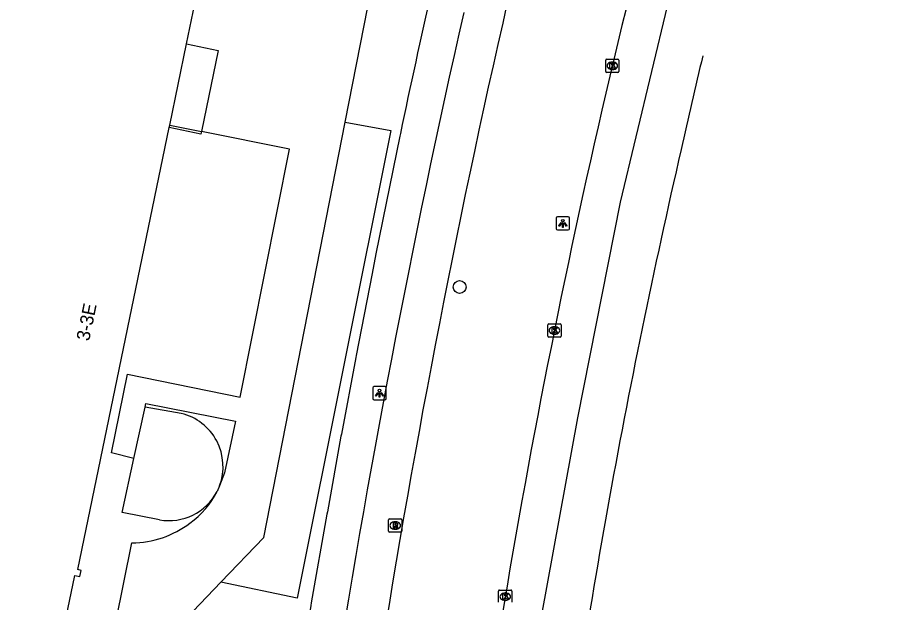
# Model space of a CAD drawing. Extents: x 161243 to 161752, y 384138 to 384885.
# Drawn here: x 161439.4 to 161506.3, y 384193.1 to 384237.2 of the extents above; entities that cross this region are included whole.
import ezdxf

# ---------------------------------------------------------------- set-up
doc = ezdxf.new("R2010")
doc.units = 0
for name, color, linetype in [('IMGEO_Boom', 7, 'Continuous'), ('IMGEO_Fietspad_gesloten', 7, 'Continuous'), ('IMGEO_Kolk', 7, 'Continuous'), ('IMGEO_Lichtpunt', 7, 'Continuous'), ('IMGEO_Muur', 7, 'Continuous'), ('IMGEO_Pand', 7, 'Continuous'), ('IMGEO_Pand_nummerreeks', 7, 'Continuous'), ('IMGEO_Parkeervlak_open', 7, 'Continuous'), ('IMGEO_Rijbaan_lokaal_gesloten', 7, 'Continuous'), ('IMGEO_Rijbaan_lokaal_open', 7, 'Continuous'), ('IMGEO_Rioolput', 7, 'Continuous'), ('IMGEO_Voetpad_open', 7, 'Continuous')]:
    doc.layers.add(name, color=color, linetype=linetype)

msp = doc.modelspace()

# ---------------------------------------------------------------- linework, layer by layer
at = {"layer": 'IMGEO_Boom'}
msp.add_circle((161472.801, 384216.873), 0.489, dxfattribs=at)
at = {"layer": 'IMGEO_Fietspad_gesloten'}
for centre, radius, start, end in [((162039.774, 384110.274), 577.749, 158.754785, 167.348346), ((162230.462, 384065.754), 776.602, 167.214855, 171.164573), ((162191.8, 384074.084), 734.013, 167.191187, 171.331495)]:
    msp.add_arc(centre, radius, start, end, dxfattribs=at)
at = {"layer": 'IMGEO_Kolk'}
for p, q in [((161483.91, 384234.081), (161484.762, 384234.081)), ((161483.835, 384233.155), (161483.835, 384234.007)), ((161484.323, 384233.861), (161484.348, 384233.861)), ((161484.836, 384234.007), (161484.836, 384233.155)), ((161484.762, 384233.081), (161483.91, 384233.081)), ((161484.346, 384233.301), (161484.321, 384233.301)), ((161479.459, 384213.165), (161479.459, 384214.017)), ((161479.534, 384214.091), (161480.386, 384214.091)), ((161480.46, 384214.017), (161480.46, 384213.165)), ((161479.947, 384213.871), (161479.972, 384213.871)), ((161480.386, 384213.091), (161479.534, 384213.091)), ((161479.97, 384213.311), (161479.945, 384213.311)), ((161475.823, 384193.985), (161476.675, 384193.985)), ((161475.748, 384193.059), (161475.748, 384193.911)), ((161476.236, 384193.765), (161476.261, 384193.765)), ((161476.749, 384193.911), (161476.749, 384193.059)), ((161476.259, 384193.205), (161476.234, 384193.205))]:
    msp.add_line(p, q, dxfattribs=at)
for points in [[(161483.91, 384234.081), (161484.762, 384234.081)], [(161483.835, 384233.155), (161483.835, 384234.007)], [(161484.156, 384233.781), (161484.279, 384233.781), (161484.279, 384233.63), (161484.409, 384233.781), (161484.573, 384233.781), (161484.427, 384233.63), (161484.58, 384233.381), (161484.428, 384233.381), (161484.343, 384233.545), (161484.279, 384233.478), (161484.279, 384233.381), (161484.156, 384233.381), (161484.156, 384233.781)], [(161484.836, 384234.007), (161484.836, 384233.155)], [(161484.762, 384233.081), (161483.91, 384233.081)], [(161479.459, 384213.165), (161479.459, 384214.017)], [(161479.534, 384214.091), (161480.386, 384214.091)], [(161480.46, 384214.017), (161480.46, 384213.165)], [(161479.78, 384213.791), (161479.903, 384213.791), (161479.903, 384213.64), (161480.033, 384213.791), (161480.197, 384213.791), (161480.051, 384213.64), (161480.204, 384213.391), (161480.052, 384213.391), (161479.967, 384213.555), (161479.903, 384213.488), (161479.903, 384213.391), (161479.78, 384213.391), (161479.78, 384213.791)], [(161480.386, 384213.091), (161479.534, 384213.091)], [(161475.823, 384193.985), (161476.675, 384193.985)], [(161475.748, 384193.059), (161475.748, 384193.911)], [(161476.069, 384193.685), (161476.192, 384193.685), (161476.192, 384193.534), (161476.322, 384193.685), (161476.486, 384193.685), (161476.34, 384193.534), (161476.493, 384193.285), (161476.341, 384193.285), (161476.256, 384193.449), (161476.192, 384193.382), (161476.192, 384193.285), (161476.069, 384193.285), (161476.069, 384193.685)], [(161476.749, 384193.911), (161476.749, 384193.059)]]:
    msp.add_lwpolyline(points, dxfattribs=at)
for centre, start, end in [((161483.912, 384234.005), 91.55205, 178.44795), ((161483.912, 384234.005), 91.55205, 178.44795), ((161484.76, 384234.005), 1.55205, 88.44795), ((161484.76, 384234.005), 1.55205, 88.44795), ((161483.912, 384233.157), 181.55205, 268.44795), ((161483.912, 384233.157), 181.55205, 268.44795), ((161484.76, 384233.157), 271.55205, 358.44795), ((161484.76, 384233.157), 271.55205, 358.44795), ((161479.536, 384214.015), 91.55205, 178.44795), ((161479.536, 384214.015), 91.55205, 178.44795), ((161480.384, 384214.015), 1.55205, 88.44795), ((161480.384, 384214.015), 1.55205, 88.44795), ((161479.536, 384213.167), 181.55205, 268.44795), ((161479.536, 384213.167), 181.55205, 268.44795), ((161480.384, 384213.167), 271.55205, 358.44795), ((161480.384, 384213.167), 271.55205, 358.44795), ((161475.825, 384193.909), 91.55205, 178.44795), ((161475.825, 384193.909), 91.55205, 178.44795), ((161476.673, 384193.909), 1.55205, 88.44795), ((161476.673, 384193.909), 1.55205, 88.44795)]:
    msp.add_arc(centre, 0.0765, start, end, dxfattribs=at)
for centre, major_axis, ratio, start_param, end_param in [((161484.322, 384233.581), (-0.387, 0.002), 0.722429, 4.712389, 7.853982), ((161484.347, 384233.581), (-0.39, 0.002), 0.717154, 1.570796, 4.712389), ((161479.946, 384213.591), (-0.387, 0.002), 0.722429, 4.712389, 7.853982), ((161479.971, 384213.591), (-0.39, 0.002), 0.717154, 1.570796, 4.712389), ((161476.235, 384193.485), (-0.387, 0.002), 0.722429, 4.712389, 7.853982), ((161476.26, 384193.485), (-0.39, 0.002), 0.717154, 1.570796, 4.712389)]:
    msp.add_ellipse(centre, major_axis=major_axis, ratio=ratio, start_param=start_param, end_param=end_param, dxfattribs=at)
at = {"layer": 'IMGEO_Lichtpunt'}
for p, q in [((161480.099, 384222.081), (161480.099, 384221.274)), ((161480.099, 384222.081), (161480.099, 384221.274)), ((161481.001, 384222.176), (161480.193, 384222.176)), ((161481.001, 384222.176), (161480.193, 384222.176)), ((161481.095, 384221.274), (161481.095, 384222.081)), ((161481.095, 384221.274), (161481.095, 384222.081)), ((161480.193, 384221.18), (161481.001, 384221.18)), ((161480.193, 384221.18), (161481.001, 384221.18)), ((161467.151, 384209.347), (161466.343, 384209.347)), ((161467.151, 384209.347), (161466.343, 384209.347)), ((161466.249, 384209.252), (161466.249, 384208.445)), ((161466.249, 384209.252), (161466.249, 384208.445)), ((161467.245, 384208.445), (161467.245, 384209.252)), ((161467.245, 384208.445), (161467.245, 384209.252)), ((161466.343, 384208.351), (161467.151, 384208.351)), ((161466.343, 384208.351), (161467.151, 384208.351))]:
    msp.add_line(p, q, dxfattribs=at)
for points in [[(161480.473, 384221.745), (161480.512, 384221.717), (161480.324, 384221.455), (161480.286, 384221.482), (161480.473, 384221.745)], [(161480.575, 384221.697), (161480.622, 384221.697), (161480.622, 384221.375), (161480.575, 384221.375), (161480.575, 384221.697)], [(161480.685, 384221.717), (161480.723, 384221.744), (161480.91, 384221.482), (161480.871, 384221.454), (161480.685, 384221.717)], [(161466.623, 384208.916), (161466.662, 384208.888), (161466.474, 384208.626), (161466.436, 384208.653), (161466.623, 384208.916)], [(161466.725, 384208.868), (161466.772, 384208.868), (161466.772, 384208.546), (161466.725, 384208.546), (161466.725, 384208.868)], [(161466.835, 384208.888), (161466.873, 384208.915), (161467.06, 384208.653), (161467.021, 384208.625), (161466.835, 384208.888)]]:
    msp.add_lwpolyline(points, dxfattribs=at)
for centre in [(161480.598, 384221.879), (161466.748, 384209.05)]:
    msp.add_circle(centre, 0.0994, dxfattribs=at)
for centre, start, end in [((161480.193, 384222.081), 90, 180), ((161480.193, 384222.081), 90, 180), ((161481.001, 384222.081), 0, 90), ((161481.001, 384222.081), 0, 90), ((161480.193, 384221.274), 180, 270), ((161480.193, 384221.274), 180, 270), ((161481.001, 384221.274), 270, 0), ((161481.001, 384221.274), 270, 360), ((161466.343, 384209.252), 90, 180), ((161466.343, 384209.252), 90, 180), ((161467.151, 384209.252), 0, 90), ((161467.151, 384209.252), 0, 90), ((161466.343, 384208.445), 180, 270), ((161466.343, 384208.445), 180, 270), ((161467.151, 384208.445), 270, 0), ((161467.151, 384208.445), 270, 360)]:
    msp.add_arc(centre, 0.0946, start, end, dxfattribs=at)
at = {"layer": 'IMGEO_Muur'}
for points in [[(161453.294, 384228.617), (161453.254, 384228.422), (161450.857, 384228.917)], [(161450.895, 384229.101), (161453.294, 384228.617)]]:
    msp.add_lwpolyline(points, dxfattribs=at)
at = {"layer": 'IMGEO_Pand'}
for points in [[(161452.162, 384235.232), (161453.42, 384241.315)], [(161450.895, 384229.101), (161452.162, 384235.232)], [(161439.412, 384174.382), (161443.732, 384195.077), (161444.116, 384194.997), (161444.215, 384195.469), (161443.954, 384195.524), (161450.857, 384228.917)], [(161450.857, 384228.917), (161450.895, 384229.101)], [(161448.196, 384203.927), (161449.046, 384207.808)], [(161451.764, 384207.323), (161449.046, 384207.808)], [(161450.119, 384199.287), (161447.3, 384199.836), (161448.196, 384203.927)], [(161454.663, 384201.86), (161454.473, 384201.437)]]:
    msp.add_lwpolyline(points, dxfattribs=at)
for centre, radius, start, end in [((161450.806, 384203.314), 4.122, 339.34786, 76.55842), ((161450.831, 384203.329), 4.104, 260.0128, 332.54741)]:
    msp.add_arc(centre, radius, start, end, dxfattribs=at)
at = {"layer": 'IMGEO_Parkeervlak_open'}
msp.add_lwpolyline([(161464.156, 384229.33), (161467.614, 384228.691), (161460.528, 384193.368), (161454.769, 384194.574)], dxfattribs=at)
at = {"layer": 'IMGEO_Rijbaan_lokaal_gesloten'}
msp.add_lwpolyline([(161638.668, 384567.921), (161627.681, 384546.777), (161605.302, 384502.824), (161593.763, 384479.586), (161574.873, 384442.021), (161545.035, 384383.956), (161539.238, 384372.041), (161525.285, 384343.063), (161517.236, 384325.784), (161510.904, 384308.827), (161504.035, 384290.582), (161498.991, 384275.235), (161492.66, 384254.201), (161489.655, 384243.039), (161484.933, 384223.293), (161481.713, 384206.981), (161478.494, 384189.488), (161475.768, 384168.523)], dxfattribs=at)
for centre, radius, start, end in [((162060.147, 384097.056), 591.775, 164.583524, 168.642877), ((161981.717, 384117.185), 504.342, 166.56914, 167.39261), ((162049.283, 384098.342), 574.404, 167.029464, 169.792421), ((162080.075, 384092.431), 612.223, 168.585748, 172.505802), ((162105.793, 384089.027), 631.67, 169.869265, 172.34975)]:
    msp.add_arc(centre, radius, start, end, dxfattribs=at)
at = {"layer": 'IMGEO_Rijbaan_lokaal_open'}
for points in [[(161464.156, 384229.33), (161465.863, 384238.046), (161462.953, 384238.76), (161465.264, 384250), (161469.159, 384268.947), (161457.031, 384271.325)], [(161452.162, 384235.232), (161454.559, 384234.736), (161453.294, 384228.617)], [(161454.769, 384194.574), (161458.012, 384197.955), (161464.156, 384229.33)], [(161448.196, 384203.927), (161446.487, 384204.343), (161447.708, 384210.294), (161456.213, 384208.564), (161459.938, 384227.276), (161453.294, 384228.617)], [(161449.046, 384207.808), (161449.095, 384208.074), (161455.874, 384206.739), (161455.036, 384202.831), (161454.663, 384201.86)], [(161439.412, 384174.382), (161443.202, 384173.582), (161448.035, 384197.539)], [(161444.823, 384163.456), (161445.81, 384167.846), (161447.397, 384174.537), (161450.553, 384190.18), (161454.769, 384194.574)]]:
    msp.add_lwpolyline(points, dxfattribs=at)
for centre, radius, start, end in [((161448.701, 384204.312), 6.449, 305.18922, 333.52156), ((161447.965, 384204.882), 7.343, 270.54385, 307.31948)]:
    msp.add_arc(centre, radius, start, end, dxfattribs=at)
at = {"layer": 'IMGEO_Rioolput'}
for p, q in [((161467.507, 384199.358), (161468.359, 384199.358)), ((161467.432, 384198.432), (161467.432, 384199.284)), ((161467.92, 384199.138), (161467.945, 384199.138)), ((161468.433, 384199.284), (161468.433, 384198.432)), ((161468.359, 384198.358), (161467.507, 384198.358)), ((161467.943, 384198.578), (161467.918, 384198.578))]:
    msp.add_line(p, q, dxfattribs=at)
for points in [[(161467.507, 384199.358), (161468.359, 384199.358)], [(161467.432, 384198.432), (161467.432, 384199.284)], [(161468.021, 384199.056), (161467.769, 384199.058), (161467.769, 384198.658)], [(161467.769, 384198.658), (161467.893, 384198.658), (161467.893, 384198.82), (161467.904, 384198.82)], [(161467.947, 384198.977), (161467.893, 384198.977), (161467.893, 384198.896)], [(161467.893, 384198.896), (161467.945, 384198.896)], [(161467.951, 384198.791), (161468.022, 384198.658), (161468.162, 384198.658), (161468.097, 384198.784)], [(161468.433, 384199.284), (161468.433, 384198.432)], [(161468.359, 384198.358), (161467.507, 384198.358)]]:
    msp.add_lwpolyline(points, dxfattribs=at)
for centre, radius, start, end in [((161467.509, 384199.282), 0.0765, 91.55205, 178.44795), ((161467.509, 384199.282), 0.0765, 91.55205, 178.44795), ((161468.357, 384199.282), 0.0765, 1.55205, 88.44795), ((161468.357, 384199.282), 0.0765, 1.55205, 88.44795), ((161467.903, 384198.767), 0.0533, 26.02933, 88.69889), ((161467.929, 384199.085), 0.19, 274.7715, 282.96867), ((161467.953, 384198.881), 0.0964, 77.00612, 93.18647), ((161467.967, 384198.938), 0.0378, 276.66336, 79.67722), ((161468.02, 384198.946), 0.109, 350.36119, 89.41601), ((161468.018, 384198.946), 0.112, 277.58423, 350.98172), ((161468.002, 384198.731), 0.108, 29.51342, 73.79051), ((161467.509, 384198.434), 0.0765, 181.55205, 268.44795), ((161467.509, 384198.434), 0.0765, 181.55205, 268.44795), ((161468.357, 384198.434), 0.0765, 271.55205, 358.44795), ((161468.357, 384198.434), 0.0765, 271.55205, 358.44795)]:
    msp.add_arc(centre, radius, start, end, dxfattribs=at)
for centre, major_axis, ratio, start_param, end_param in [((161467.919, 384198.858), (-0.387, 0.002), 0.722429, 4.712389, 7.853982), ((161467.944, 384198.858), (-0.39, 0.002), 0.717154, 1.570796, 4.712389)]:
    msp.add_ellipse(centre, major_axis=major_axis, ratio=ratio, start_param=start_param, end_param=end_param, dxfattribs=at)
at = {"layer": 'IMGEO_Voetpad_open'}
msp.add_lwpolyline([(161468.323, 384228.48), (161468.282, 384228.265), (161466.465, 384219.382), (161466.186, 384217.884), (161464.994, 384211.701), (161464.952, 384211.554), (161463.869, 384205.765), (161463.831, 384205.598), (161462.81, 384199.882), (161462.766, 384199.717), (161461.588, 384193.018), (161461.56, 384192.809), (161460.912, 384188.629)], dxfattribs=at)
msp.add_arc((162044.09, 384107.797), 588.279, 166.011457, 168.161921, dxfattribs=at)

# ---------------------------------------------------------------- texts
at = {"layer": 'IMGEO_Pand_nummerreeks'}
msp.add_text('3-3E', height=1, rotation=78.27749, dxfattribs=at).set_placement((161444.81, 384212.751))

doc.saveas('drawing.dxf')
